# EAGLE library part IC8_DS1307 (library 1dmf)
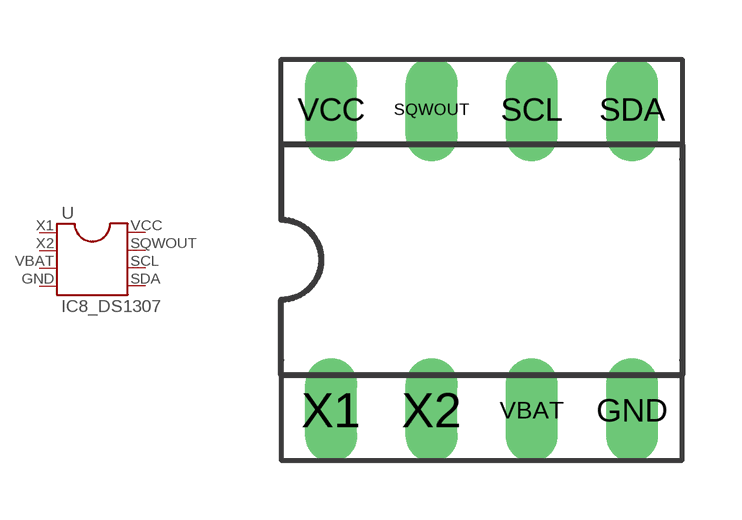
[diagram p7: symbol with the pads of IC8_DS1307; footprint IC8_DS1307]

Designator prefix -

## IC8_DS1307  [IC8_DS1307]
GND  4  pas
SCL  6  pas
SDA  5  pas
SQWOUT  7  pas
VBAT  3  pas
VCC  8  pas
X1  1  pas
X2  2  pas

## Footprint IC8_DS1307 (pad centres in mm)
drill 0.813 long: GND 3.81,-3.81; SCL 1.27,3.81; SDA 3.81,3.81; SQWOUT -1.27,3.81; VBAT 1.27,-3.81; VCC -3.81,3.81; X1 -3.81,-3.81; X2 -1.27,-3.81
